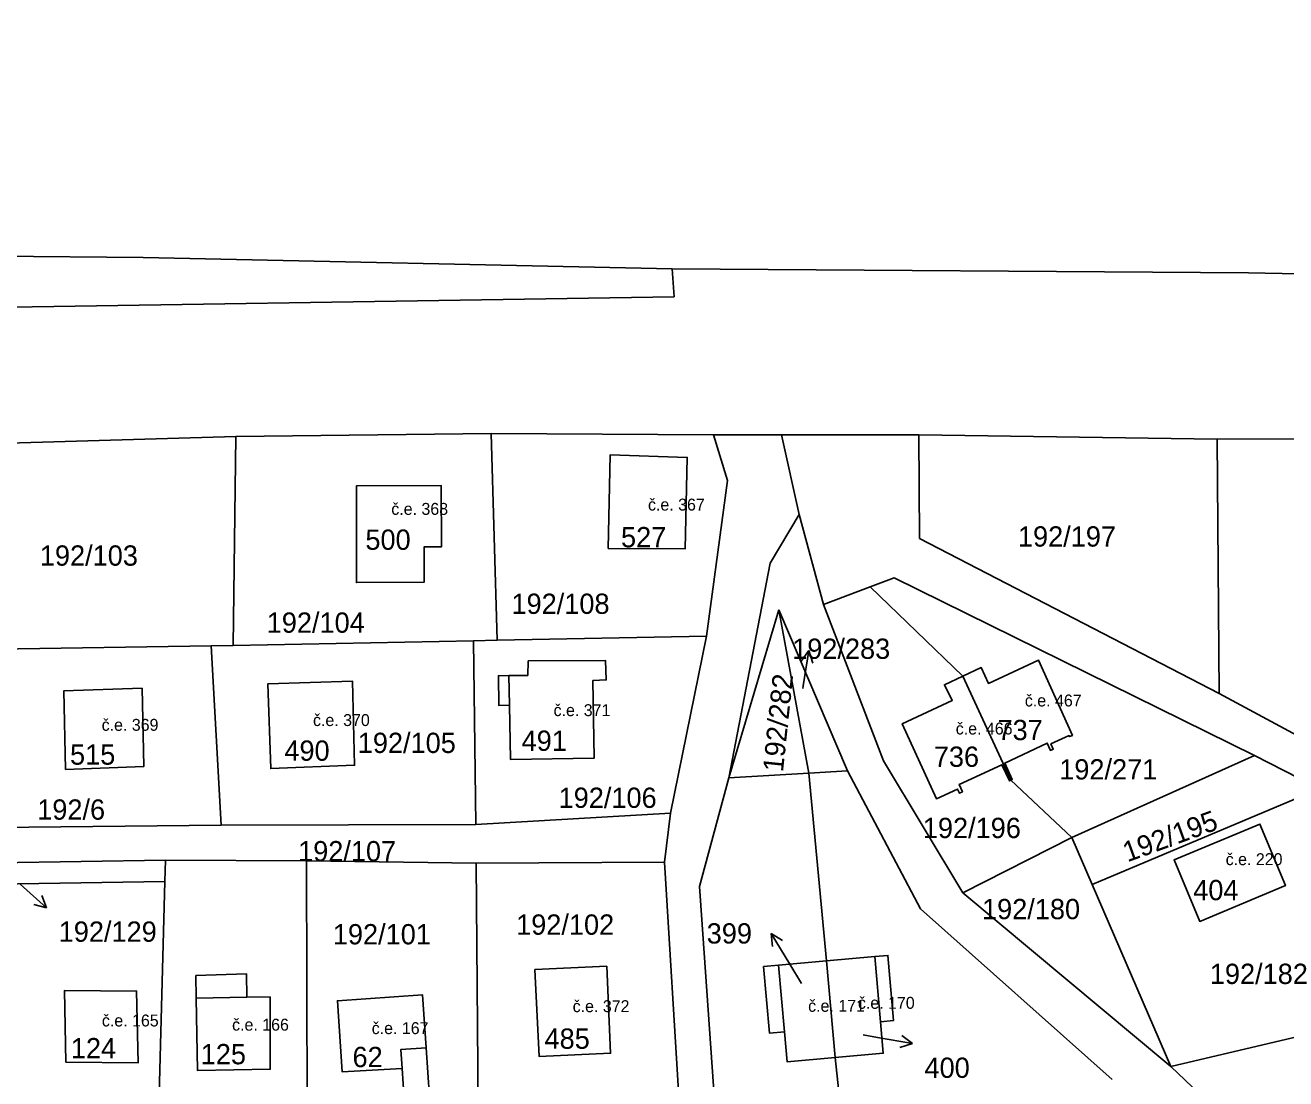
# Model space of a CAD drawing. Extents: x -887272 to -877616, y -1026687 to -1019819.
# Drawn here: x -882394.3 to -882288.7, y -1024108.6 to -1024020.3 of the extents above; entities that cross this region are included whole.
import ezdxf

# ---------------------------------------------------------------- set-up
doc = ezdxf.new("R2010")
doc.units = 0
for name, color, linetype in [('Definiční body', 7, 'Continuous'), ('Hranice parcel', 7, 'Continuous'), ('Parcelní čísla', 7, 'Continuous'), ('Polygon budovy', 7, 'Continuous'), ('Pop  PČ popisy', 7, 'Continuous'), ('Vnitřní kresba', 7, 'Continuous')]:
    doc.layers.add(name, color=color, linetype=linetype)

msp = doc.modelspace()

# ---------------------------------------------------------------- linework, layer by layer
at = {"layer": 'Hranice parcel'}
for p, q in [((-882384.42, -1024039.73), (-882445.26, -1024039.2)), ((-882340.1, -1024040.68), (-882384.42, -1024039.73)), ((-882376.66, -1024054.74), (-882355.26, -1024054.47)), ((-882355.26, -1024054.47), (-882336.63, -1024054.59)), ((-882354.76, -1024071.81), (-882355.26, -1024054.47)), ((-882376.66, -1024054.74), (-882399.93, -1024055.4)), ((-882376.88, -1024072.24), (-882376.66, -1024054.74)), ((-882330.93, -1024054.59), (-882336.63, -1024054.59)), ((-882330.93, -1024054.59), (-882319.43, -1024054.58)), ((-882329.46, -1024061.27), (-882330.93, -1024054.59)), ((-882294.43, -1024054.96), (-882319.43, -1024054.58)), ((-882273.78, -1024054.86), (-882294.43, -1024054.96)), ((-882294.27, -1024076.26), (-882294.43, -1024054.96)), ((-882327.43, -1024068.82), (-882329.46, -1024061.27)), ((-882327.43, -1024068.82), (-882323.51, -1024067.33)), ((-882315.74, -1024074.82), (-882323.51, -1024067.33)), ((-882335.35, -1024083.33), (-882331.18, -1024069.25)), ((-882328.64, -1024082.94), (-882331.18, -1024069.25)), ((-882331.18, -1024069.25), (-882325.42, -1024082.75)), ((-882378.73, -1024072.28), (-882399.46, -1024072.61)), ((-882378.73, -1024072.28), (-882376.88, -1024072.24)), ((-882377.91, -1024087.31), (-882378.73, -1024072.28)), ((-882356.76, -1024071.85), (-882376.88, -1024072.24)), ((-882354.76, -1024071.81), (-882356.76, -1024071.85)), ((-882356.55, -1024087.26), (-882356.76, -1024071.85)), ((-882337.23, -1024071.47), (-882354.76, -1024071.81)), ((-882337.23, -1024071.47), (-882340.25, -1024086.3)), ((-882311.73, -1024083.54), (-882315.74, -1024074.82)), ((-882294.27, -1024076.26), (-882285.96, -1024080.75)), ((-882291.31, -1024081.48), (-882306.6, -1024088.34)), ((-882285.87, -1024084.26), (-882291.31, -1024081.48)), ((-882335.35, -1024083.33), (-882328.64, -1024082.94)), ((-882328.64, -1024082.94), (-882325.42, -1024082.75)), ((-882327.16, -1024098.69), (-882328.64, -1024082.94)), ((-882306.6, -1024088.34), (-882311.73, -1024083.54)), ((-882285.87, -1024084.26), (-882304.9, -1024092.29)), ((-882377.91, -1024087.31), (-882356.55, -1024087.26)), ((-882356.55, -1024087.26), (-882340.25, -1024086.3)), ((-882340.25, -1024086.3), (-882340.76, -1024090.41)), ((-882398.59, -1024087.52), (-882377.91, -1024087.31)), ((-882306.6, -1024088.34), (-882315.76, -1024092.99)), ((-882304.9, -1024092.29), (-882306.6, -1024088.34)), ((-882398.79, -1024090.5), (-882382.57, -1024090.25)), ((-882382.57, -1024090.25), (-882382.62, -1024092.03)), ((-882370.74, -1024090.3), (-882382.57, -1024090.25)), ((-882370.69, -1024118.6), (-882370.74, -1024090.3)), ((-882356.54, -1024090.49), (-882370.74, -1024090.3)), ((-882356.54, -1024090.49), (-882340.76, -1024090.41)), ((-882340.76, -1024090.41), (-882339.24, -1024115.27)), ((-882356.32, -1024115.33), (-882356.54, -1024090.49)), ((-882382.62, -1024092.03), (-882398.72, -1024092.28)), ((-882383.34, -1024118.62), (-882382.62, -1024092.03)), ((-882298.33, -1024107.54), (-882304.9, -1024092.29)), ((-882298.33, -1024107.54), (-882315.76, -1024092.99)), ((-882326.44, -1024106.78), (-882327.16, -1024098.69)), ((-882325.37, -1024116.79), (-882326.44, -1024106.78)), ((-882273.27, -1024131.24), (-882298.33, -1024107.54))]:
    msp.add_line(p, q, dxfattribs=at)
for points in [[(-882340.1, -1024040.68), (-882291.8, -1024041.02), (-882266.44, -1024041.52), (-882231.92, -1024039.84), (-882208.92, -1024035.12), (-882179.22, -1024022.58), (-882174.49, -1024020.26)], [(-882603.02, -1024045.76), (-882539.56, -1024043.76), (-882473.06, -1024046.88), (-882408.1, -1024044.08), (-882339.94, -1024043.02), (-882340.1, -1024040.68)], [(-882336.63, -1024054.59), (-882335.46, -1024058.41), (-882337.23, -1024071.47)], [(-882319.43, -1024054.58), (-882319.38, -1024063.28), (-882294.27, -1024076.26)], [(-882339.02, -1024064.16), (-882338.84, -1024056.48), (-882345.3, -1024056.28), (-882345.46, -1024064.11), (-882339.02, -1024064.16)], [(-882366.57, -1024058.88), (-882366.57, -1024066.97), (-882360.88, -1024066.93), (-882360.89, -1024063.99), (-882359.44, -1024063.98), (-882359.47, -1024058.83), (-882366.57, -1024058.88)], [(-882335.35, -1024083.33), (-882331.89, -1024065.34), (-882329.46, -1024061.27)], [(-882323.51, -1024067.33), (-882321.51, -1024066.57), (-882291.31, -1024081.48)], [(-882315.76, -1024092.99), (-882322.4, -1024081.92), (-882327.43, -1024068.82)], [(-882345.63, -1024075.14), (-882345.69, -1024073.51), (-882352.16, -1024073.54), (-882352.21, -1024074.76), (-882353.78, -1024074.77), (-882354.67, -1024074.79), (-882354.63, -1024077.27), (-882353.73, -1024077.25), (-882353.65, -1024081.81), (-882346.65, -1024081.7), (-882346.75, -1024075.18), (-882345.63, -1024075.14)], [(-882315.74, -1024074.82), (-882314.2, -1024074.1), (-882313.61, -1024075.43), (-882309.42, -1024073.47), (-882306.56, -1024079.78), (-882306.8, -1024079.89), (-882306.84, -1024079.8), (-882308.37, -1024080.5), (-882308.17, -1024080.93), (-882308.41, -1024081.04), (-882308.68, -1024080.43), (-882312.23, -1024082.1), (-882311.6, -1024083.48), (-882311.73, -1024083.54)], [(-882366.72, -1024082.29), (-882366.89, -1024075.25), (-882373.99, -1024075.47), (-882373.74, -1024082.57), (-882366.72, -1024082.29)], [(-882311.73, -1024083.54), (-882311.85, -1024083.6), (-882312.48, -1024082.24), (-882316.05, -1024083.89), (-882315.78, -1024084.51), (-882316.02, -1024084.63), (-882316.19, -1024084.28), (-882317.96, -1024085.1), (-882320.82, -1024078.81), (-882316.64, -1024076.85), (-882317.29, -1024075.54), (-882315.74, -1024074.82)], [(-882391.09, -1024076.06), (-882390.93, -1024082.64), (-882384.37, -1024082.39), (-882384.53, -1024075.83), (-882391.09, -1024076.06)], [(-882325.42, -1024082.75), (-882319.29, -1024094.33), (-882303.23, -1024108.62)], [(-882336.02, -1024117.94), (-882337.81, -1024092.45), (-882335.35, -1024083.33)], [(-882290.85, -1024087.22), (-882298.05, -1024090.21), (-882295.9, -1024095.38), (-882288.71, -1024092.37), (-882290.85, -1024087.22)], [(-882327.16, -1024098.69), (-882331.2, -1024099.05), (-882332.45, -1024099.16), (-882331.95, -1024104.74), (-882330.7, -1024104.63), (-882330.48, -1024107.14), (-882326.44, -1024106.78)], [(-882326.44, -1024106.78), (-882322.41, -1024106.42), (-882322.64, -1024103.78), (-882321.55, -1024103.68), (-882322.03, -1024098.23), (-882323.13, -1024098.33), (-882327.16, -1024098.69)], [(-882373.8, -1024101.71), (-882375.74, -1024101.72), (-882375.76, -1024099.77), (-882380.01, -1024099.92), (-882379.98, -1024101.8), (-882379.88, -1024107.87), (-882373.78, -1024107.76), (-882373.8, -1024101.71)], [(-882351.61, -1024099.41), (-882351.25, -1024106.69), (-882345.26, -1024106.42), (-882345.58, -1024099.13), (-882351.61, -1024099.41)], [(-882298.33, -1024107.54), (-882281.94, -1024103.67), (-882276.26, -1024100.98)], [(-882384.98, -1024101.21), (-882391.03, -1024101.17), (-882390.91, -1024107.17), (-882384.86, -1024107.23), (-882384.98, -1024101.21)], [(-882360.43, -1024110.11), (-882360.72, -1024105.96), (-882361.02, -1024101.54), (-882368.16, -1024102.02), (-882367.76, -1024107.97), (-882362.73, -1024107.69), (-882362.56, -1024110.26), (-882360.43, -1024110.11)]]:
    msp.add_lwpolyline(points, dxfattribs=at)
at = {"layer": 'Polygon budovy'}
for points in [[(-882345.3, -1024056.28), (-882345.46, -1024064.11), (-882339.02, -1024064.16), (-882338.84, -1024056.48)], [(-882366.57, -1024066.97), (-882360.88, -1024066.93), (-882360.89, -1024063.99), (-882359.44, -1024063.98), (-882359.47, -1024058.83), (-882366.57, -1024058.88)], [(-882353.65, -1024081.81), (-882346.65, -1024081.7), (-882346.75, -1024075.18), (-882345.63, -1024075.14), (-882345.69, -1024073.51), (-882352.16, -1024073.54), (-882352.21, -1024074.76), (-882353.78, -1024074.77), (-882353.73, -1024077.25)], [(-882314.2, -1024074.1), (-882315.74, -1024074.82), (-882311.73, -1024083.54), (-882311.6, -1024083.48), (-882312.23, -1024082.1), (-882308.68, -1024080.43), (-882308.41, -1024081.04), (-882308.17, -1024080.93), (-882308.37, -1024080.5), (-882306.84, -1024079.8), (-882306.8, -1024079.89), (-882306.56, -1024079.78), (-882309.42, -1024073.47), (-882313.61, -1024075.43)], [(-882366.89, -1024075.25), (-882373.99, -1024075.47), (-882373.74, -1024082.57), (-882366.72, -1024082.29)], [(-882320.82, -1024078.81), (-882317.96, -1024085.1), (-882316.19, -1024084.28), (-882316.02, -1024084.63), (-882315.78, -1024084.51), (-882316.05, -1024083.89), (-882312.48, -1024082.24), (-882311.85, -1024083.6), (-882311.73, -1024083.54), (-882315.74, -1024074.82), (-882317.29, -1024075.54), (-882316.64, -1024076.85)], [(-882384.53, -1024075.83), (-882391.09, -1024076.06), (-882390.93, -1024082.64), (-882384.37, -1024082.39)], [(-882298.05, -1024090.21), (-882295.9, -1024095.38), (-882288.71, -1024092.37), (-882290.85, -1024087.22)], [(-882330.48, -1024107.14), (-882326.44, -1024106.78), (-882327.16, -1024098.69), (-882331.2, -1024099.05), (-882330.7, -1024104.63)], [(-882326.44, -1024106.78), (-882322.41, -1024106.42), (-882322.64, -1024103.78), (-882323.13, -1024098.33), (-882327.16, -1024098.69)], [(-882351.61, -1024099.41), (-882351.25, -1024106.69), (-882345.26, -1024106.42), (-882345.58, -1024099.13)], [(-882391.03, -1024101.17), (-882390.91, -1024107.17), (-882384.86, -1024107.23), (-882384.98, -1024101.21)], [(-882373.78, -1024107.76), (-882373.8, -1024101.71), (-882375.74, -1024101.72), (-882379.98, -1024101.8), (-882379.88, -1024107.87)], [(-882361.02, -1024101.54), (-882368.16, -1024102.02), (-882367.76, -1024107.97), (-882362.73, -1024107.69), (-882362.84, -1024106.11), (-882360.72, -1024105.96)]]:
    msp.add_lwpolyline(points, close=True, dxfattribs=at)
at = {"layer": 'Pop  PČ popisy'}
for p, q in [((-882328.65, -1024072.66), (-882329.3, -1024073.57)), ((-882329.12, -1024075.62), (-882328.65, -1024072.66)), ((-882328.65, -1024072.66), (-882328.31, -1024073.72)), ((-882329.16, -1024075.86), (-882329.12, -1024075.62)), ((-882394.75, -1024092.24), (-882392.52, -1024094.25)), ((-882392.52, -1024094.25), (-882392.93, -1024093.21)), ((-882392.52, -1024094.25), (-882393.6, -1024093.95)), ((-882330.25, -1024098.95), (-882331.8, -1024096.38)), ((-882331.8, -1024096.38), (-882330.85, -1024096.98)), ((-882331.8, -1024096.38), (-882331.71, -1024097.49)), ((-882329.28, -1024100.57), (-882330.25, -1024098.95)), ((-882324.09, -1024104.89), (-882322.91, -1024105.1)), ((-882322.91, -1024105.1), (-882319.96, -1024105.62)), ((-882319.96, -1024105.62), (-882320.85, -1024104.95)), ((-882319.96, -1024105.62), (-882321.03, -1024105.94))]:
    msp.add_line(p, q, dxfattribs=at)
at = {"layer": 'Vnitřní kresba'}
for p, q in [((-882353.73, -1024077.25), (-882353.78, -1024074.77)), ((-882323.13, -1024098.33), (-882322.64, -1024103.78)), ((-882331.2, -1024099.05), (-882330.7, -1024104.63)), ((-882375.74, -1024101.72), (-882379.98, -1024101.8)), ((-882362.84, -1024106.11), (-882360.72, -1024105.96)), ((-882362.84, -1024106.11), (-882362.73, -1024107.69))]:
    msp.add_line(p, q, dxfattribs=at)

# ---------------------------------------------------------------- texts
at = {"layer": 'Definiční body'}
for s, p in [('č.e. 368', (-882363.64, -1024061.3)), ('č.e. 367', (-882342.13, -1024060.94)), ('č.e. 467', (-882310.55, -1024077.36)), ('č.e. 371', (-882350.04, -1024078.17)), ('č.e. 369', (-882387.91, -1024079.4)), ('č.e. 370', (-882370.2, -1024079)), ('č.e. 466', (-882316.34, -1024079.71)), ('č.e. 220', (-882293.72, -1024090.66)), ('č.e. 372', (-882348.44, -1024102.98)), ('č.e. 171', (-882328.71, -1024102.95)), ('č.e. 170', (-882324.54, -1024102.7)), ('č.e. 165', (-882387.89, -1024104.18)), ('č.e. 166', (-882376.98, -1024104.53)), ('č.e. 167', (-882365.28, -1024104.82))]:
    msp.add_text(s, height=1, dxfattribs=at).set_placement(p)
at = {"layer": 'Parcelní čísla'}
for s, p in [('500', (-882365.81, -1024064.23)), ('527', (-882344.39, -1024064.02)), ('192/197', (-882311.13, -1024063.96)), ('192/103', (-882393.09, -1024065.56)), ('192/108', (-882353.57, -1024069.6)), ('192/104', (-882374.08, -1024071.18)), ('192/283', (-882330.05, -1024073.37)), ('737', (-882312.84, -1024080.18)), ('192/105', (-882366.45, -1024081.26)), ('491', (-882352.72, -1024081.08)), ('515', (-882390.56, -1024082.24)), ('490', (-882372.6, -1024081.91)), ('736', (-882318.18, -1024082.42)), ('192/271', (-882307.67, -1024083.48)), ('192/106', (-882349.62, -1024085.86)), ('192/6', (-882393.31, -1024086.85)), ('192/196', (-882319.1, -1024088.39)), ('192/107', (-882371.45, -1024090.34)), ('404', (-882296.44, -1024093.6)), ('192/180', (-882314.14, -1024095.19)), ('192/129', (-882391.51, -1024097.08)), ('192/101', (-882368.54, -1024097.3)), ('192/102', (-882353.18, -1024096.49)), ('399', (-882337.21, -1024097.23)), ('192/182', (-882295.05, -1024100.62)), ('124', (-882390.49, -1024106.85)), ('485', (-882350.8, -1024106.05)), ('125', (-882379.61, -1024107.35)), ('62', (-882366.89, -1024107.59)), ('400', (-882318.96, -1024108.49))]:
    msp.add_text(s, height=1.7, dxfattribs=at).set_placement(p)
for s, rotation, p in [('192/282', 84, (-882330.82, -1024082.9)), ('192/195', 20, (-882301.96, -1024090.43))]:
    msp.add_text(s, height=1.7, rotation=rotation, dxfattribs=at).set_placement(p)

doc.saveas('drawing.dxf')
